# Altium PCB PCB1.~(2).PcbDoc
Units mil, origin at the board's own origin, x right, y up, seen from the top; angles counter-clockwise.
Board outline 6000 x 4000 mil, 2 copper layers (Top Layer, Bottom Layer); 1 components, 44 nets, 2 pads, 0 vias.
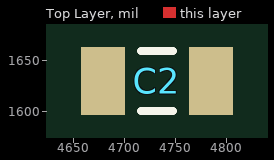
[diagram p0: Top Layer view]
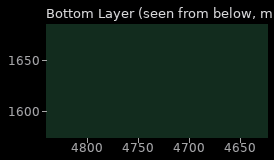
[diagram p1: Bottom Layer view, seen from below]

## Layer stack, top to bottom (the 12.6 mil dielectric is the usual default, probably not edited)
Top Solder: solder mask 0.4, Solder Resist, Dk 3.5
Top Layer: signal copper 1.4
Dielectric 1: dielectric 12.6, FR-4, Dk 4.8
Bottom Layer: signal copper 1.4
Bottom Solder: solder mask 0.4, Solder Resist, Dk 3.5

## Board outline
1000,1000 7000,1000 7000,5000 1000,5000

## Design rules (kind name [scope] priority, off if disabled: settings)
Clearance [All] p1: gap=10
PolygonConnect [All] p1: connectstyle=Relief reliefconductorwidth=10 reliefentries=4 polygonreliefangle="90 Angle" airgapwidth=10
RoomDefinition BeaconMCU [InComponentClass('BeaconMCU')] p1: confinementstyle=ConfineIn formatcopy=TRUE lockcomponents=FALSE outline 4641.85,1585 4821.85,1585 4821.85,1775 4641.85,1775
RoutingVias [All] p1: holewidth=28 width=50 viastyle="Through Hole" minholewidth=28 minwidth=50 maxholewidth=28 maxwidth=50
SolderMaskExpansion [All] p1: expansion=4
Width [All] p1: maxlimit=10 minlimit=10 preferedwidth=10
30 further rules are at their usual default settings.

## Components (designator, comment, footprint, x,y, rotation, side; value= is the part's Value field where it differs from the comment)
C2 "" C1206 4731.85,1630 r0 top

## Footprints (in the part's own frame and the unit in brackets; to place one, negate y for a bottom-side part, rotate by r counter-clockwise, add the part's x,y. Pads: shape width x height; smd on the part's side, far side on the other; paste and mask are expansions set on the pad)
C1206 [mm] "Chip Capacitor, Body 3.2x1.6mm, IPC High Density"
  rect 1.1x1.7 smd: 1(-1.35,0) 2(1.35,0)
  silkscreen extent -0.4,-0.75 0.4,0.75, body extent -1.7,-0.9 1.7,0.9, height 1.3

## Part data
C2: library part "Cap Semi", "Capacitor (Semiconductor SIM Model)"

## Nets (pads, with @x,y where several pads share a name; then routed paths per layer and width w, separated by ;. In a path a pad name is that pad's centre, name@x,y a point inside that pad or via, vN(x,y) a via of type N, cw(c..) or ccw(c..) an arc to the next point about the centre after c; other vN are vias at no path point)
ANTENNA_DEBUG: 
BUS3_GPIO0: 
BUS3_GPIO1: 
BUS3_GPIO2: 
BUS3_GPIO3: 
BUS6: 
EN_R_PA_BEACON: 
GND: C2.1
GPIO0_BEACON_RADIO: 
GPIO1_BEACON_RADIO: 
I2C_SCL: 
I2C_SDA: 
NetC2_2: C2.2
NetTP9_1: 
NetTP10_1: 
NetTP11_1: 
NetTP12_1: 
NetTP13_1: 
NetTP14_1: 
NetTP15_1: 
NetTP16_1: 
NetTP17_1: 
NetTP18_1: 
NetTP19_1: 
NetTP20_1: 
NetTP21_1: 
NIRQ_BEACON_RADIO: 
R_EPS/BEACON: 
RF_SIM_UART_TX: 
SDN_BEACON_RADIO: 
SYSTEM_ON: 
TCK: 
TDO/TDI: 
USCI_A0_CLK_1: 
USCI_A0_MISO_1: 
USCI_A0_MOSI_1: 
USCI_A0_STE_1: 
USCI_A1_RX_MCU: 
USCI_A1_TX_MCU: 
VREF_BEACON: 
XIN_BEACON: 
XOUT_BEACON: 
XT2IN_BEACON: 
XT2OUT_BEACON: 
